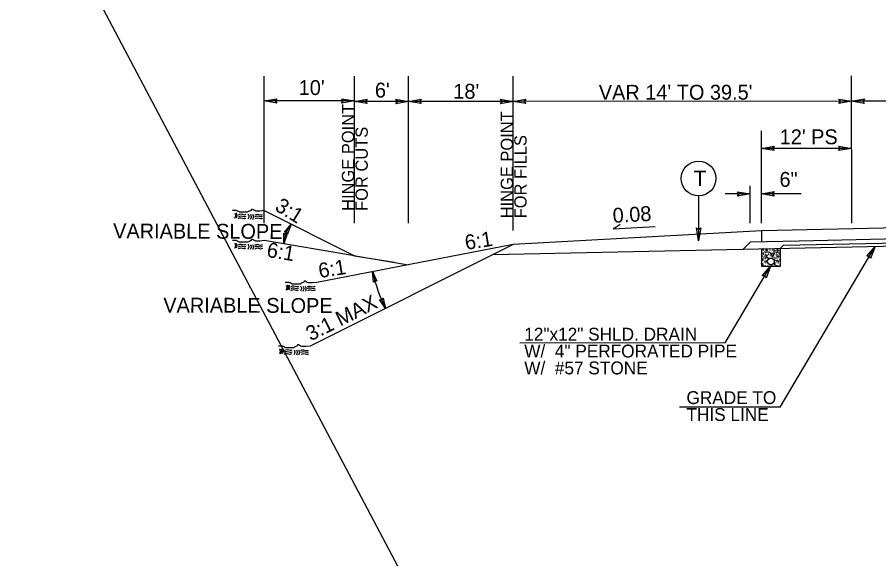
# Model space of a CAD drawing. Extents: x 2241081 to 2251104, y 658534 to 663427.
# Drawn here: x 2245637.7 to 2246115, y 662109.1 to 662409 of the extents above; entities that cross this region are included whole.
import ezdxf

# ---------------------------------------------------------------- set-up
doc = ezdxf.new("R2010")
doc.units = 0
for name, color, linetype in [('Old_Level_1', 7, 'Continuous'), ('Old_Level_11', 7, 'Continuous'), ('Old_Level_2', 7, 'Continuous'), ('Old_Level_3', 7, 'Continuous'), ('Prop Dimension', 7, 'Continuous'), ('Prop Dimension Text', 7, 'Continuous'), ('Prop PHM Text', 7, 'Continuous'), ('Typical Arrow Superelevation CELL', 7, 'Continuous'), ('Typical Berm Information CELL', 7, 'Continuous'), ('Typical Curb CELL', 7, 'Continuous'), ('Typical Hinge Slope Interstate CELL', 7, 'Continuous'), ('Typical ID Circle CELL', 7, 'Continuous'), ('Typical Terminator CELL', 7, 'Continuous'), ('Typical Text ID Circle CELL', 7, 'Continuous')]:
    doc.layers.add(name, color=color, linetype=linetype)

msp = doc.modelspace()

# ---------------------------------------------------------------- linework, layer by layer
at = {"layer": 'Old_Level_1'}
for p, q in [((2245774.51, 662301.99), (2245824.51, 662276.98)), ((2245824.51, 662276.98), (2245774.51, 662285.32)), ((2245912.52, 662283.15), (2245803.69, 662262.2)), ((2245824.51, 662276.98), (2245846.51, 662273.32))]:
    msp.add_line(p, q, dxfattribs=at)
for points in [[(2245774.51, 662301.99), (2245772.04, 662301.68), (2245771.43, 662301.68), (2245770.5, 662301.68), (2245769.89, 662301.68), (2245769.27, 662301.99), (2245768.65, 662302.29), (2245768.04, 662302.6), (2245767.42, 662302.6), (2245767.11, 662301.99), (2245766.5, 662301.68), (2245765.88, 662301.37), (2245765.26, 662301.06), (2245764.65, 662301.06), (2245764.03, 662301.06), (2245763.41, 662301.06), (2245762.8, 662301.06), (2245762.18, 662301.06), (2245761.57, 662301.06), (2245760.95, 662301.06), (2245760.33, 662301.37), (2245759.72, 662301.68), (2245759.1, 662301.99), (2245758.18, 662301.99), (2245757.56, 662301.99), (2245756.94, 662301.99)], [(2245774.51, 662285.32), (2245772.04, 662285.01), (2245771.43, 662285.01), (2245770.5, 662285.01), (2245769.89, 662285.01), (2245769.27, 662285.32), (2245768.65, 662285.63), (2245768.04, 662285.94), (2245767.42, 662285.94), (2245767.11, 662285.32), (2245766.5, 662285.01), (2245765.88, 662284.7), (2245765.26, 662284.4), (2245764.65, 662284.4), (2245764.03, 662284.4), (2245763.41, 662284.4), (2245762.8, 662284.4), (2245762.18, 662284.4), (2245761.57, 662284.4), (2245760.95, 662284.4), (2245760.33, 662284.7), (2245759.72, 662285.01), (2245759.1, 662285.32), (2245758.18, 662285.32), (2245757.56, 662285.32), (2245756.94, 662285.32)], [(2245803.69, 662262.2), (2245801.22, 662261.9), (2245800.61, 662261.9), (2245799.68, 662261.9), (2245799.06, 662261.9), (2245798.45, 662262.2), (2245797.83, 662262.51), (2245797.22, 662262.82), (2245796.6, 662262.82), (2245796.29, 662262.2), (2245795.67, 662261.9), (2245795.06, 662261.59), (2245794.44, 662261.28), (2245793.83, 662261.28), (2245793.21, 662261.28), (2245792.59, 662261.28), (2245791.98, 662261.28), (2245791.36, 662261.28), (2245790.75, 662261.28), (2245790.13, 662261.28), (2245789.51, 662261.59), (2245788.9, 662261.9), (2245788.28, 662262.2), (2245787.36, 662262.2), (2245786.74, 662262.2), (2245786.12, 662262.2)], [(2245800.02, 662226.9), (2245797.56, 662226.59), (2245796.94, 662226.59), (2245796.02, 662226.59), (2245795.4, 662226.59), (2245794.78, 662226.9), (2245794.17, 662227.21), (2245793.55, 662227.52), (2245792.93, 662227.52), (2245792.63, 662226.9), (2245792.01, 662226.59), (2245791.39, 662226.28), (2245790.78, 662225.98), (2245790.16, 662225.98), (2245789.54, 662225.98), (2245788.93, 662225.98), (2245788.31, 662225.98), (2245787.7, 662225.98), (2245787.08, 662225.98), (2245786.46, 662225.98), (2245785.85, 662226.28), (2245785.23, 662226.59), (2245784.62, 662226.9), (2245783.69, 662226.9), (2245783.07, 662226.9), (2245782.46, 662226.9)]]:
    msp.add_lwpolyline(points, dxfattribs=at)
for points in [[(2245758.2, 662300.54), (2245758.62, 662299.29), (2245758.16, 662297.65)], [(2245758.2, 662300.54), (2245758.62, 662299.29), (2245758.16, 662297.65)], [(2245758.98, 662300.62), (2245759.4, 662299.38), (2245758.95, 662297.73)], [(2245758.98, 662300.62), (2245759.4, 662299.38), (2245758.95, 662297.73)], [(2245760.18, 662297.55), (2245761.69, 662297.97), (2245763.28, 662297.58), (2245764.43, 662297.83)], [(2245760.18, 662297.55), (2245761.69, 662297.97), (2245763.28, 662297.58), (2245764.43, 662297.83)], [(2245760.3, 662298.61), (2245761.81, 662299.03), (2245763.39, 662298.63), (2245764.53, 662298.88)], [(2245760.3, 662298.61), (2245761.81, 662299.03), (2245763.39, 662298.63), (2245764.53, 662298.88)], [(2245760.31, 662299.65), (2245761.81, 662300.08), (2245763.4, 662299.68), (2245764.54, 662299.94)], [(2245760.31, 662299.65), (2245761.81, 662300.08), (2245763.4, 662299.68), (2245764.54, 662299.94)], [(2245765.57, 662300.01), (2245765.98, 662298.77), (2245765.54, 662297.12)], [(2245765.57, 662300.01), (2245765.98, 662298.77), (2245765.54, 662297.12)], [(2245766.88, 662299.91), (2245767.3, 662298.66), (2245766.85, 662297.01)], [(2245766.88, 662299.91), (2245767.3, 662298.66), (2245766.85, 662297.01)], [(2245768.09, 662299.8), (2245768.51, 662298.55), (2245768.06, 662296.91)], [(2245768.09, 662299.8), (2245768.51, 662298.55), (2245768.06, 662296.91)], [(2245769.33, 662299.51), (2245770.84, 662299.94), (2245772.43, 662299.53), (2245773.57, 662299.79)], [(2245769.33, 662299.51), (2245770.84, 662299.94), (2245772.43, 662299.53), (2245773.57, 662299.79)], [(2245769.37, 662298.57), (2245770.88, 662299), (2245772.46, 662298.59), (2245773.61, 662298.85)], [(2245769.37, 662298.57), (2245770.88, 662299), (2245772.46, 662298.59), (2245773.61, 662298.85)], [(2245769.53, 662297.47), (2245771.03, 662297.9), (2245772.62, 662297.5), (2245773.77, 662297.76)], [(2245769.53, 662297.47), (2245771.03, 662297.9), (2245772.62, 662297.5), (2245773.77, 662297.76)], [(2245758.2, 662283.87), (2245758.62, 662282.63), (2245758.16, 662280.98)], [(2245758.2, 662283.87), (2245758.62, 662282.63), (2245758.16, 662280.98)], [(2245758.98, 662283.96), (2245759.4, 662282.71), (2245758.95, 662281.07)], [(2245758.98, 662283.96), (2245759.4, 662282.71), (2245758.95, 662281.07)], [(2245760.31, 662282.99), (2245761.81, 662283.42), (2245763.4, 662283.01), (2245764.54, 662283.27)], [(2245760.31, 662282.99), (2245761.81, 662283.42), (2245763.4, 662283.01), (2245764.54, 662283.27)], [(2245765.57, 662283.34), (2245765.98, 662282.1), (2245765.54, 662280.45)], [(2245765.57, 662283.34), (2245765.98, 662282.1), (2245765.54, 662280.45)], [(2245766.88, 662283.24), (2245767.3, 662282), (2245766.85, 662280.35)], [(2245766.88, 662283.24), (2245767.3, 662282), (2245766.85, 662280.35)], [(2245768.09, 662283.13), (2245768.51, 662281.89), (2245768.06, 662280.24)], [(2245768.09, 662283.13), (2245768.51, 662281.89), (2245768.06, 662280.24)], [(2245769.33, 662282.85), (2245770.84, 662283.27), (2245772.43, 662282.87), (2245773.57, 662283.12)], [(2245769.33, 662282.85), (2245770.84, 662283.27), (2245772.43, 662282.87), (2245773.57, 662283.12)], [(2245760.18, 662280.88), (2245761.69, 662281.31), (2245763.28, 662280.91), (2245764.43, 662281.17)], [(2245760.18, 662280.88), (2245761.69, 662281.31), (2245763.28, 662280.91), (2245764.43, 662281.17)], [(2245760.3, 662281.94), (2245761.81, 662282.37), (2245763.39, 662281.96), (2245764.53, 662282.22)], [(2245760.3, 662281.94), (2245761.81, 662282.37), (2245763.39, 662281.96), (2245764.53, 662282.22)], [(2245769.37, 662281.9), (2245770.88, 662282.33), (2245772.46, 662281.92), (2245773.61, 662282.18)], [(2245769.37, 662281.9), (2245770.88, 662282.33), (2245772.46, 662281.92), (2245773.61, 662282.18)], [(2245769.53, 662280.81), (2245771.03, 662281.24), (2245772.62, 662280.83), (2245773.77, 662281.09)], [(2245769.53, 662280.81), (2245771.03, 662281.24), (2245772.62, 662280.83), (2245773.77, 662281.09)]]:
    msp.add_spline(points, degree=3, dxfattribs=at)
at = {"layer": 'Old_Level_11'}
for p, q in [((2246060.33, 662193.14), (2246112.98, 662282.05)), ((2246029.88, 662228.66), (2246055.08, 662271.22))]:
    msp.add_line(p, q, dxfattribs=at)
at = {"layer": 'Old_Level_2'}
for p, q in [((2247232.05, 659489.1), (2245149.47, 663427.07)), ((2246160.02, 662293.06), (2246050.02, 662290.7)), ((2246050.02, 662290.7), (2245912.52, 662283.15)), ((2246050.02, 662290.7), (2246050.02, 662284.65)), ((2246043.83, 662284.52), (2246039.79, 662280.48)), ((2246160.02, 662283.06), (2246039.79, 662280.48)), ((2246070.93, 662285.1), (2246043.83, 662284.52)), ((2246160.02, 662284.65), (2246062.06, 662282.55)), ((2246160.02, 662287.01), (2246070.93, 662285.1)), ((2246039.79, 662280.48), (2245901.25, 662277.52)), ((2246050.02, 662280.7), (2246050.02, 662271.22)), ((2246062.06, 662282.55), (2246060.43, 662280.92)), ((2246060.43, 662280.92), (2246060.43, 662271.22)), ((2246050.02, 662271.22), (2246060.43, 662271.22))]:
    msp.add_line(p, q, dxfattribs=at)
msp.add_circle((2246055.26, 662273.72), 1.87, dxfattribs=at)
for points in [[(2245786.65, 662260.62), (2245787.07, 662259.38), (2245786.61, 662257.73)], [(2245786.65, 662260.62), (2245787.07, 662259.38), (2245786.61, 662257.73)], [(2245787.38, 662260.76), (2245787.8, 662259.51), (2245787.34, 662257.87)], [(2245787.38, 662260.76), (2245787.8, 662259.51), (2245787.34, 662257.87)], [(2245788.16, 662260.84), (2245788.58, 662259.6), (2245788.13, 662257.95)], [(2245788.16, 662260.84), (2245788.58, 662259.6), (2245788.13, 662257.95)], [(2245789.48, 662258.83), (2245790.98, 662259.25), (2245792.57, 662258.84), (2245793.71, 662259.1)], [(2245789.48, 662258.83), (2245790.98, 662259.25), (2245792.57, 662258.84), (2245793.71, 662259.1)], [(2245789.49, 662259.87), (2245790.98, 662260.3), (2245792.58, 662259.9), (2245793.72, 662260.16)], [(2245789.49, 662259.87), (2245790.98, 662260.3), (2245792.58, 662259.9), (2245793.72, 662260.16)], [(2245794.74, 662260.23), (2245795.16, 662258.99), (2245794.71, 662257.34)], [(2245794.74, 662260.23), (2245795.16, 662258.99), (2245794.71, 662257.34)], [(2245796.06, 662260.12), (2245796.48, 662258.88), (2245796.03, 662257.23)], [(2245796.06, 662260.12), (2245796.48, 662258.88), (2245796.03, 662257.23)], [(2245797.27, 662260.02), (2245797.69, 662258.77), (2245797.24, 662257.13)], [(2245797.27, 662260.02), (2245797.69, 662258.77), (2245797.24, 662257.13)], [(2245798.51, 662259.73), (2245800.02, 662260.16), (2245801.6, 662259.75), (2245802.75, 662260.01)], [(2245798.51, 662259.73), (2245800.02, 662260.16), (2245801.6, 662259.75), (2245802.75, 662260.01)], [(2245798.55, 662258.78), (2245800.06, 662259.22), (2245801.64, 662258.81), (2245802.79, 662259.07)], [(2245798.55, 662258.78), (2245800.06, 662259.22), (2245801.64, 662258.81), (2245802.79, 662259.07)], [(2245789.36, 662257.77), (2245790.86, 662258.19), (2245792.46, 662257.8), (2245793.6, 662258.05)], [(2245789.36, 662257.77), (2245790.86, 662258.19), (2245792.46, 662257.8), (2245793.6, 662258.05)], [(2245798.71, 662257.69), (2245800.21, 662258.12), (2245801.8, 662257.72), (2245802.95, 662257.98)], [(2245783.71, 662225.45), (2245784.13, 662224.21), (2245783.67, 662222.56)], [(2245783.71, 662225.45), (2245784.13, 662224.21), (2245783.67, 662222.56)], [(2245784.49, 662225.54), (2245784.92, 662224.29), (2245784.46, 662222.65)], [(2245784.49, 662225.54), (2245784.92, 662224.29), (2245784.46, 662222.65)], [(2245782.98, 662225.31), (2245783.41, 662224.07), (2245782.95, 662222.42)], [(2245782.98, 662225.31), (2245783.41, 662224.07), (2245782.95, 662222.42)], [(2245785.7, 662222.46), (2245787.2, 662222.89), (2245788.8, 662222.49), (2245789.94, 662222.75)], [(2245785.7, 662222.46), (2245787.2, 662222.89), (2245788.8, 662222.49), (2245789.94, 662222.75)], [(2245785.81, 662223.52), (2245787.32, 662223.95), (2245788.9, 662223.54), (2245790.05, 662223.8)], [(2245785.81, 662223.52), (2245787.32, 662223.95), (2245788.9, 662223.54), (2245790.05, 662223.8)], [(2245785.82, 662224.57), (2245787.32, 662225), (2245788.92, 662224.59), (2245790.06, 662224.85)], [(2245785.82, 662224.57), (2245787.32, 662225), (2245788.92, 662224.59), (2245790.06, 662224.85)], [(2245791.08, 662224.92), (2245791.5, 662223.68), (2245791.05, 662222.03)], [(2245791.08, 662224.92), (2245791.5, 662223.68), (2245791.05, 662222.03)], [(2245792.39, 662224.82), (2245792.81, 662223.58), (2245792.36, 662221.93)], [(2245792.39, 662224.82), (2245792.81, 662223.58), (2245792.36, 662221.93)], [(2245793.6, 662224.71), (2245794.03, 662223.47), (2245793.57, 662221.82)], [(2245793.6, 662224.71), (2245794.03, 662223.47), (2245793.57, 662221.82)], [(2245794.85, 662224.43), (2245796.36, 662224.86), (2245797.94, 662224.45), (2245799.09, 662224.7)], [(2245794.85, 662224.43), (2245796.36, 662224.86), (2245797.94, 662224.45), (2245799.09, 662224.7)], [(2245794.89, 662223.48), (2245796.4, 662223.92), (2245797.98, 662223.51), (2245799.13, 662223.76)], [(2245794.89, 662223.48), (2245796.4, 662223.92), (2245797.98, 662223.51), (2245799.13, 662223.76)], [(2245795.04, 662222.39), (2245796.54, 662222.82), (2245798.14, 662222.41), (2245799.28, 662222.67)]]:
    msp.add_spline(points, degree=3, dxfattribs=at)
at = {"layer": 'Prop Dimension'}
for centre, radius, start, end in [((2245804.45, 662282.66), 19.12, 141.6676, 177.4305), ((2245914.01, 662284.57), 81.05, 191.6788, 206.9901)]:
    msp.add_arc(centre, radius, start, end, dxfattribs=at)
at = {"layer": 'Prop Dimension Text'}
for p, q in [((2245774.51, 662295), (2245774.51, 662376.47)), ((2245824.51, 662295), (2245824.51, 662376.47)), ((2245854.51, 662295), (2245854.51, 662376.47)), ((2245912.52, 662290.88), (2245912.46, 662376.47)), ((2246100.01, 662294.97), (2246099.96, 662376.58)), ((2246100.01, 662294.97), (2246099.96, 662376.58)), ((2245774.51, 662362.78), (2245774.51, 662362.78)), ((2245824.51, 662362.66), (2245774.51, 662362.66)), ((2245824.51, 662362.78), (2245824.51, 662362.78)), ((2245854.51, 662362.4), (2245824.51, 662362.4)), ((2245912.52, 662362.4), (2245854.51, 662362.4)), ((2246099.97, 662362.51), (2245912.47, 662362.4)), ((2246159.97, 662362.55), (2246099.97, 662362.51)), ((2246050.01, 662294.94), (2246049.98, 662346.04)), ((2246099.87, 662336.39), (2246049.99, 662336.35)), ((2246043.83, 662294.94), (2246043.83, 662315.59)), ((2246043.83, 662311.2), (2246029.96, 662311.19)), ((2246072.01, 662311.22), (2246050, 662311.21)), ((2246029.88, 662228.66), (2245916.22, 662228.59)), ((2246060.33, 662193.14), (2246004.7, 662193.11))]:
    msp.add_line(p, q, dxfattribs=at)
at = {"layer": 'Typical Arrow Superelevation CELL'}
for q in [(2245971.7, 662294.41), (2245991.14, 662293.18)]:
    msp.add_line((2245967.87, 662291.9), q, dxfattribs=at)
at = {"layer": 'Typical Curb CELL'}
for p, q in [((2246051.28, 662278.45), (2246050.85, 662278.37)), ((2246050.85, 662278.37), (2246051.07, 662277.71)), ((2246051.07, 662277.71), (2246051.28, 662278.45)), ((2246052.83, 662280.34), (2246053.08, 662279.45)), ((2246053.32, 662279.99), (2246052.83, 662280.34)), ((2246053.08, 662279.45), (2246053.32, 662279.99)), ((2246055.46, 662278.39), (2246055.02, 662278.31)), ((2246055.02, 662278.31), (2246055.24, 662277.65)), ((2246055.24, 662277.65), (2246055.46, 662278.39)), ((2246057.22, 662278.28), (2246056.79, 662278.2)), ((2246056.79, 662278.2), (2246057.01, 662277.55)), ((2246057, 662280.28), (2246057.25, 662279.39)), ((2246057.49, 662279.93), (2246057, 662280.28)), ((2246057.01, 662277.55), (2246057.22, 662278.28)), ((2246057.25, 662279.39), (2246057.49, 662279.93)), ((2246058.76, 662280.18), (2246059.01, 662279.29)), ((2246059.26, 662279.83), (2246058.76, 662280.18)), ((2246059.01, 662279.29), (2246059.26, 662279.83)), ((2246050.92, 662275.11), (2246050.49, 662275.03)), ((2246050.49, 662275.03), (2246050.71, 662274.38)), ((2246050.71, 662274.38), (2246050.92, 662275.11)), ((2246052.46, 662277.01), (2246052.71, 662276.12)), ((2246052.96, 662276.66), (2246052.46, 662277.01)), ((2246052.55, 662274.2), (2246052.8, 662273.31)), ((2246053.04, 662273.85), (2246052.55, 662274.2)), ((2246052.71, 662276.12), (2246052.96, 662276.66)), ((2246052.8, 662273.31), (2246053.04, 662273.85)), ((2246055.73, 662277.33), (2246055.98, 662276.44)), ((2246056.22, 662276.98), (2246055.73, 662277.33)), ((2246055.98, 662276.44), (2246056.22, 662276.98)), ((2246057.43, 662275.03), (2246056.99, 662274.94)), ((2246056.99, 662274.94), (2246057.21, 662274.29)), ((2246057.21, 662274.29), (2246057.43, 662275.03)), ((2246058.97, 662276.92), (2246059.22, 662276.03)), ((2246059.46, 662276.57), (2246058.97, 662276.92)), ((2246059.06, 662274.38), (2246059.31, 662273.49)), ((2246059.55, 662274.03), (2246059.06, 662274.38)), ((2246059.22, 662276.03), (2246059.46, 662276.57)), ((2246059.31, 662273.49), (2246059.55, 662274.03)), ((2246051.01, 662272.31), (2246050.57, 662272.23)), ((2246050.57, 662272.23), (2246050.79, 662271.57)), ((2246050.79, 662271.57), (2246051.01, 662272.31)), ((2246057.52, 662272.48), (2246057.08, 662272.4)), ((2246057.08, 662272.4), (2246057.3, 662271.75)), ((2246057.3, 662271.75), (2246057.52, 662272.48))]:
    msp.add_line(p, q, dxfattribs=at)
for centre in [(2246050.32, 662278.41), (2246050.42, 662278.88), (2246050.46, 662280.28), (2246050.55, 662280.1), (2246051.26, 662280.07), (2246051.48, 662277.85), (2246051.61, 662279.13), (2246052.15, 662279.99), (2246052.42, 662279.21), (2246052.51, 662278.64), (2246052.88, 662280.67), (2246053.32, 662279.02), (2246053.89, 662279.88), (2246054, 662278.23), (2246054.19, 662279.04), (2246054.5, 662278.35), (2246054.59, 662278.82), (2246054.63, 662280.22), (2246054.73, 662280.04), (2246055.43, 662280.01), (2246055.65, 662277.79), (2246055.78, 662279.07), (2246056.26, 662278.24), (2246056.33, 662279.93), (2246056.35, 662278.71), (2246056.4, 662280.11), (2246056.49, 662279.93), (2246056.6, 662279.15), (2246056.68, 662278.58), (2246057.06, 662280.61), (2246057.19, 662279.91), (2246057.49, 662278.96), (2246057.55, 662278.96), (2246058.06, 662279.83), (2246058.09, 662279.83), (2246058.17, 662278.17), (2246058.36, 662279.04), (2246058.36, 662278.98), (2246058.44, 662278.47), (2246058.82, 662280.5), (2246059.25, 662278.85), (2246059.82, 662279.72), (2246059.93, 662278.06), (2246060.12, 662278.88), (2246050.1, 662276.94), (2246050.18, 662274.14), (2246050.19, 662276.76), (2246050.28, 662273.96), (2246050.32, 662277.48), (2246050.89, 662276.74), (2246050.98, 662273.93), (2246051.11, 662274.51), (2246051.25, 662275.79), (2246051.79, 662276.66), (2246051.88, 662273.85), (2246051.98, 662274.27), (2246052.06, 662275.87), (2246052.14, 662275.3), (2246052.15, 662273.07), (2246052.34, 662277.61), (2246052.52, 662277.33), (2246052.61, 662274.53), (2246052.95, 662275.68), (2246053.23, 662275.39), (2246053.23, 662274.47), (2246053.32, 662275.87), (2246053.36, 662277.26), (2246053.46, 662277.09), (2246053.52, 662276.55), (2246053.63, 662274.89), (2246053.82, 662275.71), (2246053.91, 662277.5), (2246054.16, 662277.06), (2246054.5, 662277.43), (2246054.51, 662276.11), (2246055.06, 662276.98), (2246055.33, 662276.19), (2246055.41, 662275.62), (2246055.79, 662277.65), (2246056.22, 662276), (2246056.26, 662277.32), (2246056.52, 662277.55), (2246056.56, 662275.46), (2246056.6, 662276.85), (2246056.7, 662276.68), (2246056.79, 662276.87), (2246056.9, 662275.22), (2246057.09, 662276.03), (2246057.26, 662273.74), (2246057.4, 662276.65), (2246057.41, 662277.68), (2246057.49, 662274.11), (2246057.62, 662274.43), (2246057.75, 662275.7), (2246057.84, 662273.16), (2246058.09, 662277.44), (2246058.28, 662277.44), (2246058.3, 662276.57), (2246058.38, 662274.03), (2246058.49, 662274.18), (2246058.57, 662275.78), (2246058.65, 662275.21), (2246058.66, 662273.24), (2246059.03, 662277.25), (2246059.12, 662274.7), (2246059.46, 662275.59), (2246059.55, 662273.05), (2246059.85, 662277.33), (2246060.03, 662276.46), (2246060.06, 662274.07), (2246060.12, 662273.92), (2246060.14, 662274.81), (2246060.33, 662275.62), (2246050.14, 662272.74), (2246051.2, 662271.71), (2246051.33, 662272.99), (2246052.07, 662271.47), (2246052.23, 662272.5), (2246053.04, 662272.88), (2246053.64, 662271.36), (2246053.7, 662272.27), (2246053.7, 662271.34), (2246053.72, 662272.09), (2246054.85, 662271.71), (2246055.71, 662271.47), (2246056.56, 662271.52), (2246057.29, 662271.36), (2246057.37, 662272.09), (2246057.56, 662272.9), (2246057.71, 662271.89), (2246058.57, 662271.64), (2246058.74, 662272.67), (2246060.15, 662271.53), (2246060.23, 662272.27)]:
    msp.add_circle(centre, 0.0381, dxfattribs=at)
at = {"layer": 'Typical Hinge Slope Interstate CELL'}
for p, q in [((2245912.52, 662283.15), (2245800.02, 662226.9)), ((2245824.01, 662277.07), (2245854.51, 662271.98))]:
    msp.add_line(p, q, dxfattribs=at)
at = {"layer": 'Typical ID Circle CELL'}
msp.add_line((2246015.21, 662310.14), (2246015.21, 662285.28), dxfattribs=at)
msp.add_circle((2246015.21, 662319.75), 9.62, dxfattribs=at)
at = {"layer": 'Typical Terminator CELL'}
for points in [[(2245781.54, 662361.45), (2245774.51, 662362.66), (2245781.57, 662363.91), (2245780.68, 662362.66)], [(2245817.48, 662363.87), (2245824.51, 662362.66), (2245817.44, 662361.41), (2245818.33, 662362.66)], [(2246107, 662361.31), (2246099.97, 662362.51), (2246107.04, 662363.77), (2246106.14, 662362.52)], [(2245831.54, 662361.19), (2245824.51, 662362.4), (2245831.57, 662363.65), (2245830.68, 662362.4)], [(2245847.48, 662363.61), (2245854.51, 662362.4), (2245847.44, 662361.15), (2245848.33, 662362.4)], [(2245861.54, 662361.19), (2245854.51, 662362.4), (2245861.57, 662363.65), (2245860.68, 662362.4)], [(2245905.49, 662363.61), (2245912.52, 662362.4), (2245905.45, 662361.15), (2245906.35, 662362.4)], [(2245919.5, 662361.19), (2245912.47, 662362.4), (2245919.54, 662363.65), (2245918.64, 662362.4)], [(2246092.94, 662363.72), (2246099.97, 662362.51), (2246092.91, 662361.26), (2246093.8, 662362.51)], [(2246057.02, 662335.15), (2246049.99, 662336.35), (2246057.06, 662337.61), (2246056.16, 662336.36)], [(2246092.83, 662337.59), (2246099.87, 662336.39), (2246092.8, 662335.13), (2246093.69, 662336.38)], [(2246036.8, 662312.41), (2246043.83, 662311.2), (2246036.76, 662309.95), (2246037.66, 662311.2)], [(2246057.04, 662310), (2246050, 662311.21), (2246057.07, 662312.46), (2246056.18, 662311.21)], [(2245785.79, 662289.95), (2245789.45, 662294.51), (2245787.54, 662288.94), (2245787, 662290.08)], [(2246016.42, 662292.31), (2246015.21, 662285.28), (2246013.96, 662292.35), (2246015.21, 662291.45)], [(2245787.34, 662289.01), (2245785.35, 662283.51), (2245785.36, 662289.4), (2245786.24, 662288.5)], [(2246108.35, 662276.62), (2246112.98, 662282.05), (2246110.45, 662275.33), (2246109.83, 662276.74)], [(2246050.46, 662265.79), (2246055.08, 662271.22), (2246052.56, 662264.5), (2246051.94, 662265.91)], [(2245835.03, 662262.32), (2245834.63, 662268.16), (2245837, 662262.77), (2245835.83, 662263.24)], [(2245840.38, 662253.46), (2245841.78, 662247.78), (2245838.51, 662252.68), (2245839.75, 662252.42)]]:
    msp.add_lwpolyline(points, close=True, dxfattribs=at)

# ---------------------------------------------------------------- texts
at = {"layer": 'Old_Level_3'}
for s, height, p in [('12"x12" SHLD. DRAIN', 7.1311, (2245918.62, 662229.93)), ('W/  4" PERFORATED PIPE', 7.1311, (2245918.62, 662220.59)), ('W/  #57 STONE', 7.1311, (2245918.62, 662211.24)), ('GRADE TO', 7.131, (2246008.47, 662194.8)), ('THIS LINE', 7.131, (2246008.47, 662185.45))]:
    msp.add_text(s, height=height, rotation=359.9999, dxfattribs=at).set_placement(p)
at = {"layer": 'Prop Dimension Text'}
for s, rotation, p in [("10'", 359.9999, (2245793.65, 662365.93)), ("6'", 359.9999, (2245835.87, 662364.53)), ("18'", 359.9999, (2245879.31, 662363.87)), ("VAR 14' TO 39.5'", 0.0349, (2245959.91, 662363.32)), ("12' PS", 0.0349, (2246060.13, 662338.66)), ('6"', 0.0349, (2246060.02, 662315.09)), ('6:1', 8.8656, (2245886.37, 662280.11)), ('6:1', 8.8656, (2245805.25, 662264.53))]:
    msp.add_text(s, height=8.25, rotation=rotation, dxfattribs=at).set_placement(p)
at = {"layer": 'Prop PHM Text'}
for s, height, p in [('HINGE POINT', 6.8193, (2245824.41, 662301.77)), ('HINGE POINT', 6.8193, (2245912.42, 662297.65)), ('FOR CUTS', 6.819, (2245831.92, 662301.77)), ('FOR FILLS', 6.819, (2245919.93, 662297.65))]:
    msp.add_text(s, height=height, rotation=89.9999, dxfattribs=at).set_placement(p)
at = {"layer": 'Typical Berm Information CELL'}
msp.add_text('0.08', height=8.25, rotation=3.1445, dxfattribs=at).set_placement((2245967.82, 662295.11))
at = {"layer": 'Typical Hinge Slope Interstate CELL'}
for s, rotation, p in [('3:1', 328.4414, (2245779.89, 662302.51)), ('VARIABLE SLOPE', 359.8157, (2245690.85, 662286.57)), ('6:1', 350.5376, (2245775.56, 662276.38)), ('3:1 MAX', 26.565, (2245800.27, 662229.48)), ('VARIABLE SLOPE', 359.8157, (2245718.64, 662245.5))]:
    msp.add_text(s, height=8.25, rotation=rotation, dxfattribs=at).set_placement(p)
at = {"layer": 'Typical Text ID Circle CELL'}
msp.add_text('T', height=8.61, rotation=359.9999, dxfattribs=at).set_placement((2246012.45, 662315.48))

doc.saveas('drawing.dxf')
